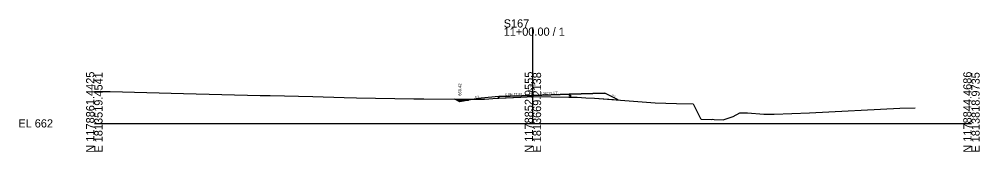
# Model space of a CAD drawing. Extents: x -26 to 6803, y -10 to 1023.
# Drawn here: x -25.7 to 302.8, y 490.3 to 535.6 of the extents above; entities that cross this region are included whole.
import ezdxf

# ---------------------------------------------------------------- set-up
doc = ezdxf.new("R2010")
doc.units = 0
for name, color, linetype in [('Default', 7, 'Continuous'), ('RD_GPK_XS_Cell', 7, 'Continuous'), ('RD_XS_Base', 7, 'Continuous'), ('RD_XS_EarthShd', 7, 'Continuous'), ('RD_XS_ExGround', 7, 'Continuous'), ('RD_XS_Misc_Line', 7, 'Continuous'), ('RD_XS_Pave', 7, 'Continuous'), ('RD_XS_TieSlope', 7, 'Continuous'), ('RD_XS_TX_Elev_EX', 7, 'Continuous'), ('RD_XS_TX_Elev_PR', 7, 'Continuous'), ('RD_XS_TX_Slope', 7, 'Continuous')]:
    doc.layers.add(name, color=color, linetype=linetype)

msp = doc.modelspace()

# ---------------------------------------------------------------- linework, layer by layer
at = {"layer": 'Default'}
for p, q in [((138.33, 509.14), (150, 509.54)), ((150, 509.54), (162.36, 509.94))]:
    msp.add_line(p, q, dxfattribs=at)
at = {"layer": 'RD_GPK_XS_Cell'}
for p, q in [((150, 500), (150, 532.74)), ((0, 500), (150, 500)), ((150, 500), (300, 500))]:
    msp.add_line(p, q, dxfattribs=at)
at = {"layer": 'RD_XS_Base'}
for p, q in [((162.24, 508.94), (162.24, 509)), ((162.36, 508.94), (162.24, 508.94))]:
    msp.add_line(p, q, dxfattribs=at)
at = {"layer": 'RD_XS_EarthShd'}
for p, q in [((162.36, 509.94), (174.58, 510.34)), ((138.33, 509.14), (132.33, 508.64))]:
    msp.add_line(p, q, dxfattribs=at)
at = {"layer": 'RD_XS_ExGround'}
for p, q in [((0, 510.91), (5.4, 510.88)), ((5.4, 510.88), (30.5, 510.2)), ((30.5, 510.2), (56.74, 509.54)), ((56.74, 509.54), (60.18, 509.57)), ((60.18, 509.57), (74.68, 509.24)), ((74.68, 509.24), (85.43, 508.81)), ((85.43, 508.81), (89.62, 508.74)), ((89.62, 508.74), (109.26, 508.39)), ((109.26, 508.39), (111.56, 508.35)), ((111.56, 508.35), (112.73, 508.34)), ((112.73, 508.34), (131.5, 508.22)), ((131.5, 508.22), (132.22, 508.25)), ((132.22, 508.25), (133.4, 508.31)), ((133.4, 508.31), (137.76, 508.6)), ((137.76, 508.6), (145.82, 508.96)), ((145.82, 508.96), (150.23, 509.17)), ((150.23, 509.17), (162.3, 509)), ((162.3, 509), (163.67, 508.98)), ((163.67, 508.98), (165.12, 508.97)), ((165.12, 508.97), (168.12, 508.78)), ((168.12, 508.78), (171.06, 508.67)), ((171.06, 508.67), (191.82, 507.06)), ((191.82, 507.06), (199.12, 506.76)), ((199.12, 506.76), (204.8, 506.68)), ((204.8, 506.68), (207.29, 501.67)), ((218.51, 502.39), (220.74, 503.64)), ((220.74, 503.64), (223.41, 503.58)), ((223.41, 503.58), (228.98, 503.19)), ((228.98, 503.19), (232.48, 503.14)), ((232.48, 503.14), (244.57, 503.63)), ((244.57, 503.63), (275.48, 505.23)), ((275.48, 505.23), (280.76, 505.31)), ((207.29, 501.67), (207.6, 501.39)), ((207.6, 501.39), (210.92, 501.35)), ((210.92, 501.35), (211.4, 501.41)), ((211.4, 501.41), (212.02, 501.29)), ((212.02, 501.29), (215.11, 501.25)), ((215.11, 501.25), (218.51, 502.39))]:
    msp.add_line(p, q, dxfattribs=at)
at = {"layer": 'RD_XS_Misc_Line'}
for points in [[(162.24, 509), (162.3, 509), (162.86, 508.99), (162.86, 509.6), (162.36, 509.61), (162.36, 509.94), (150, 509.54), (138.33, 509.14), (138.33, 508.62), (145.82, 508.96), (150.23, 509.17)], [(162.24, 509), (162.3, 509), (162.86, 508.99), (162.86, 509.6), (162.36, 509.61), (162.36, 509.94), (150, 509.54), (138.33, 509.14), (138.33, 508.62), (145.82, 508.96), (150.23, 509.17)], [(162.24, 509), (162.3, 509), (162.86, 508.99), (162.86, 509.6), (162.36, 509.61), (162.36, 509.94), (150, 509.54), (138.33, 509.14), (138.33, 508.62), (145.82, 508.96), (150.23, 509.17)], [(162.36, 509.61), (162.36, 509.94), (150, 509.54), (138.33, 509.14), (138.33, 508.62), (145.82, 508.96), (150.23, 509.17), (162.24, 509), (162.3, 509), (162.86, 508.99), (162.86, 509.6)], [(162.36, 509.61), (162.36, 509.94), (150, 509.54), (138.33, 509.14), (138.33, 508.62), (145.82, 508.96), (150.23, 509.17), (162.24, 509), (162.3, 509), (162.86, 508.99), (162.86, 509.6)], [(162.86, 508.99), (163.67, 508.98), (165.12, 508.97), (168.12, 508.78), (171.06, 508.67), (179.18, 508.04), (174.58, 510.34), (162.36, 509.94), (162.36, 509.61), (162.86, 509.6)], [(162.86, 508.99), (163.67, 508.98), (165.12, 508.97), (168.12, 508.78), (171.06, 508.67), (179.18, 508.04), (174.58, 510.34), (162.36, 509.94), (162.36, 509.61), (162.86, 509.6)], [(162.86, 508.99), (163.67, 508.98), (165.12, 508.97), (168.12, 508.78), (171.06, 508.67), (179.18, 508.04), (174.58, 510.34), (162.36, 509.94), (162.36, 509.61), (162.86, 509.6)], [(179.18, 508.04), (174.58, 510.34), (162.36, 509.94), (162.36, 509.61), (162.86, 509.6), (162.86, 508.99), (163.67, 508.98), (165.12, 508.97), (168.12, 508.78), (171.06, 508.67)], [(179.18, 508.04), (174.58, 510.34), (162.36, 509.94), (162.36, 509.61), (162.86, 509.6), (162.86, 508.99), (163.67, 508.98), (165.12, 508.97), (168.12, 508.78), (171.06, 508.67)], [(129.89, 508.23), (125, 507.42), (123.29, 508.28)], [(129.89, 508.23), (131.5, 508.22), (132.22, 508.25), (133.4, 508.31), (137.76, 508.6), (138.33, 508.62), (138.33, 509.14), (132.33, 508.64)], [(129.89, 508.23), (131.5, 508.22), (132.22, 508.25), (133.4, 508.31), (137.76, 508.6), (138.33, 508.62), (138.33, 509.14), (132.33, 508.64)], [(129.89, 508.23), (131.5, 508.22), (132.22, 508.25), (133.4, 508.31), (137.76, 508.6), (138.33, 508.62), (138.33, 509.14), (132.33, 508.64)], [(132.33, 508.64), (129.89, 508.23), (131.5, 508.22), (132.22, 508.25), (133.4, 508.31), (137.76, 508.6), (138.33, 508.62), (138.33, 509.14)], [(132.33, 508.64), (129.89, 508.23), (131.5, 508.22), (132.22, 508.25), (133.4, 508.31), (137.76, 508.6), (138.33, 508.62), (138.33, 509.14)], [(162.24, 509), (162.3, 509), (162.86, 508.99), (162.86, 508.93), (162.36, 508.94), (162.24, 508.94)], [(162.24, 509), (162.3, 509), (162.86, 508.99), (162.86, 508.93), (162.36, 508.94), (162.24, 508.94)], [(162.24, 509), (162.3, 509), (162.86, 508.99), (162.86, 508.93), (162.36, 508.94), (162.24, 508.94)], [(162.86, 508.93), (162.86, 508.99), (162.3, 509), (162.24, 509), (162.24, 508.94), (162.36, 508.94)], [(162.86, 508.93), (162.86, 508.99), (162.3, 509), (162.24, 509), (162.24, 508.94), (162.36, 508.94)]]:
    msp.add_lwpolyline(points, close=True, dxfattribs=at)
at = {"layer": 'RD_XS_Pave'}
for p, q in [((162.36, 509.61), (162.36, 509.94)), ((162.86, 509.6), (162.36, 509.61)), ((162.86, 508.93), (162.86, 509.6)), ((138.33, 509.14), (138.33, 508.62)), ((162.36, 508.94), (162.86, 508.93))]:
    msp.add_line(p, q, dxfattribs=at)
at = {"layer": 'RD_XS_TieSlope'}
msp.add_line((179.18, 508.04), (174.58, 510.34), dxfattribs=at)
at = {"layer": 'RD_XS_TX_Elev_EX'}
for p, q in [((125, 507.42), (124, 507.92)), ((124, 507.92), (128, 507.92)), ((128, 507.92), (125, 507.42))]:
    msp.add_line(p, q, dxfattribs=at)

# ---------------------------------------------------------------- texts
at = {"layer": 'RD_GPK_XS_Cell'}
for s, p in [('S167', (140, 532.74)), ('11+00.00 / 1', (140, 529.94)), ('EL 662', (-26, 498.6))]:
    msp.add_text(s, height=2.8, dxfattribs=at).set_placement(p)
for s, p in [('N 1178861.4425', (0, 490)), ('E 1813519.4541', (2.8, 490)), ('N 1178852.9555', (150, 490)), ('E 1813669.2138', (152.8, 490)), ('N 1178844.4686', (300, 490)), ('E 1813818.9735', (302.8, 490))]:
    msp.add_text(s, height=2.8, rotation=90, dxfattribs=at).set_placement(p)
at = {"layer": 'RD_XS_TX_Elev_EX'}
msp.add_text('671.17', height=0.8, rotation=90, dxfattribs=at).set_placement((149.86, 510))
at = {"layer": 'RD_XS_TX_Elev_PR'}
for s, height, p in [('669.42', 1, (125.5, 509.42)), ('671.54', 0.8, (150.88, 510.53))]:
    msp.add_text(s, height=height, rotation=90, dxfattribs=at).set_placement(p)
at = {"layer": 'RD_XS_TX_Slope'}
for s, rotation, p in [('6:1', 14.0362, (130.35, 508.54)), ('0.034 FT./FT.', 1.9705, (140.56, 509.47)), ('0.032 FT./FT.', 1.857, (152.5, 509.87)), ('2:1', 333.4349, (176.79, 509.32))]:
    msp.add_text(s, height=0.75, rotation=rotation, dxfattribs=at).set_placement(p)

doc.saveas('drawing.dxf')
